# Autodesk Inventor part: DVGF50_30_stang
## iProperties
Created: 2010-04
Part Number: DVGF50_30_stang
Document SubType Name: Modeling
Designer: TB
Mass: 234.531 g
Surface Area: 317.029 cm^2
Volume: 234.531 cm^3
Density: 1 g/cm^3
Author: TB
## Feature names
1. Revolution1
2. Fillet1
3. Revolution2
4. Extrusion1
5. Extrusion2
6. Chamfer1
7. Extrusion3
8. Chamfer3
9. Chamfer4
